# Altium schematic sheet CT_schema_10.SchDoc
size 281 x 153 mm
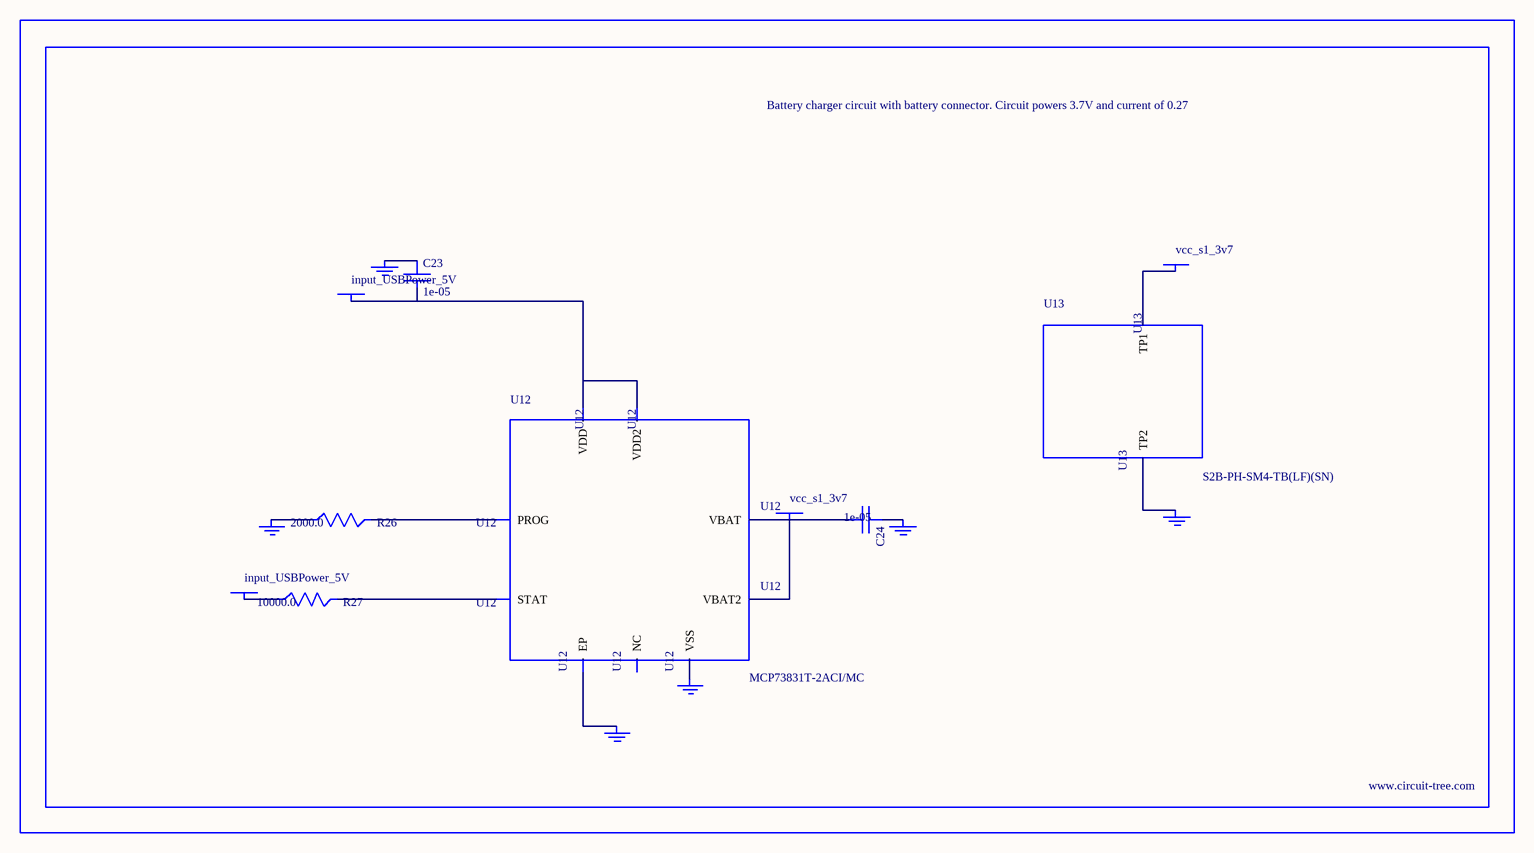
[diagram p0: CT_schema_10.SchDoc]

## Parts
BORDER9  (no value)
C23  1e-05  [C1206]
C24  1e-05  [C1206]
GND_INSTANCE_9_0  (no value)
GND_INSTANCE_9_1  (no value)
GND_INSTANCE_9_2  (no value)
GND_INSTANCE_9_3  (no value)
GND_INSTANCE_9_4  (no value)
GND_INSTANCE_9_5  (no value)
POWER_INSTANCE_9_0  input_USBPower_5V
POWER_INSTANCE_9_1  input_USBPower_5V
POWER_INSTANCE_9_2  vcc_s1_3v7
POWER_INSTANCE_9_3  vcc_s1_3v7
R26  2000.0  [R0603]
R27  10000.0  [R0603]
U12  MCP73831T-2ACI/MC  [DFN8_2X3MC]
U13  S2B-PH-SM4-TB(LF)(SN)  [JST-2-SMD]

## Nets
NetC23_1: C23.1 GND_INSTANCE_9_0.0(GND)
NetC23_2: C23.2 POWER_INSTANCE_9_0.0(PWR) U12.1(VDD) U12.2(VDD2)
NetC24_1: C24.1 GND_INSTANCE_9_1.0(GND)
NetC24_2: C24.2 POWER_INSTANCE_9_2.0(PWR) U12.3(VBAT) U12.4(VBAT2)
NetGND_INSTANCE_9_2_0: GND_INSTANCE_9_2.0(GND) R26.1
NetGND_INSTANCE_9_3_0: GND_INSTANCE_9_3.0(GND) U12.9(EP)
NetGND_INSTANCE_9_4_0: GND_INSTANCE_9_4.0(GND) U12.6(VSS)
NetGND_INSTANCE_9_5_0: GND_INSTANCE_9_5.0(GND) U13.2(TP2)
NetPOWER_INSTANCE_9_1_0: POWER_INSTANCE_9_1.0(PWR) R27.1
NetPOWER_INSTANCE_9_3_0: POWER_INSTANCE_9_3.0(PWR) U13.1(TP1)
NetR26_2: R26.2 U12.8(PROG)
NetR27_2: R27.2 U12.5(STAT)

Not connected (* = marked no-connect by the designer): U12 7(NC)

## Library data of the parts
BORDER9 = BORDER_PAGE9
C23 C24 = C1206C106K3RACTU
GND_INSTANCE_9_0-GND_INSTANCE_9_5 = GND
POWER_INSTANCE_9_0-POWER_INSTANCE_9_3 = PWR
R26 = RC0603JR-072KL
R27 = RC0603JR-0710KL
